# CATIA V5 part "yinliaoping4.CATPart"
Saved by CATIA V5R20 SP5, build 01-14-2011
Part number: 饮料瓶
Material "Multicoloured Flag"
Bounding box of the stored display mesh (mm): x -25 to 27, y -25 to 25, z 0 to 110
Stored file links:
  E:\0308\yinliaoping4.CATPart
  C:\Program Files\Dassault Systemes\B20\intel_a\startup\materials\Catalog.CATMaterial
  C:\Program Files\Dassault Systemes\B20\intel_a\startup\materials\chessboard.jpg
  C:\Program Files\Dassault Systemes\B20\intel_a\startup\materials\DS_star.jpg
  C:\Program Files\Dassault Systemes\B20\intel_a\startup\materials\solar_panel.jpg
  C:\Program Files\Dassault Systemes\B20\intel_a\startup\materials\sunset.jpg
  C:\Program Files\Dassault Systemes\B20\intel_a\startup\materials\summer_sky.jpg
  C:\Program Files\Dassault Systemes\B20\intel_a\startup\materials\raw_polystyren.jpg
  C:\Program Files\Dassault Systemes\B20\intel_a\startup\materials\strip_wall.jpg
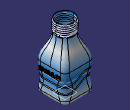
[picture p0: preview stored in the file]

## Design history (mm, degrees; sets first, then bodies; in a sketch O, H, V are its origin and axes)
Set1
  Sketch1 on xy-plane, origin (0, 0, 0), H (1, 0, 0), V (0, 1, 0)
    line L1 (25, 25) -> (25, -25)
    line L2 (25, -25) -> (-25, -25)
    line L3 (-25, -25) -> (-25, 25)
    line L4 (-25, 25) -> (25, 25)
    distance L2 L4 = 50
    distance L1 L3 = 50
    vertical: L1 V, L3 V
    horizontal: L2 H, L4 H
    equidistance: L1 L3 O, L2 L4 O
  Sketch2 on face of Pad1 from Sketch1.L2, origin (0, -25, 0), H (1, 0, 0), V (0, 0, 1)
    spline S1 through (-30, 20) (-10, 30) (10, 20) (30, 20)
  Extrude1: Element1 Sketch2, Lim1 20, Lim2 60
  Sketch3 on face of Pad1 from Sketch1.L2, origin (0, -25, 0), H (1, 0, 0), V (0, 0, 1)
    spline S1 through (-30, 30) (-10, 40) (10, 30) (30, 30)
  Extrude2: Element1 Sketch3, Lim1 56, Lim2 56
  MultiSel1: CommonCtxFeats ({extract ExtractElem face of Pad1 from Sketch1.L2}; {extract ExtractElem face of Fillet1}; {extract ExtractElem face of Pad1 from Sketch1.L1}; {extract ExtractElem face of Fillet1}; {extract ExtractElem face of Pad1 from Sketch1.L4}; {extract ExtractElem face of Fillet1}; {extract ExtractElem face of Pad1 from Sketch1.L3}; {extract ExtractElem face of Fillet1})
  MultiSel2: CommonCtxFeats ({extract ExtractElem face of Pad1 from Sketch1.L3}; {extract ExtractElem face of Fillet1}; {extract ExtractElem face of Pad1 from Sketch1.L2}; {extract ExtractElem face of Fillet1}; {extract ExtractElem face of Pad1 from Sketch1.L1}; {extract ExtractElem face of Fillet1}; {extract ExtractElem face of Pad1 from Sketch1.L4}; {extract ExtractElem face of Fillet1})
  Join1: Elements ({intersect ToIntersect1 {extract ExtractElem face of Pad1 from Sketch1.L3}, ToIntersect2 Extrude1}; {intersect ToIntersect1 {extract ExtractElem face of Fillet1}, ToIntersect2 Extrude1}; {intersect ToIntersect1 {extract ExtractElem face of Pad1 from Sketch1.L2}, ToIntersect2 Extrude1}; {intersect ToIntersect1 {extract ExtractElem face of Fillet1}, ToIntersect2 Extrude1}; {intersect ToIntersect1 {extract ExtractElem face of Pad1 from Sketch1.L1}, ToIntersect2 Extrude1}; {intersect ToIntersect1 {extract ExtractElem face of Fillet1}, ToIntersect2 Extrude1}; {intersect ToIntersect1 {extract ExtractElem face of Pad1 from Sketch1.L4}, ToIntersect2 Extrude1}; {intersect ToIntersect1 {extract ExtractElem face of Fillet1}, ToIntersect2 Extrude1})
  Join2: Elements ({intersect ToIntersect1 {extract ExtractElem face of Pad1 from Sketch1.L2}, ToIntersect2 Extrude2}; {intersect ToIntersect1 {extract ExtractElem face of Fillet1}, ToIntersect2 Extrude2}; {intersect ToIntersect1 {extract ExtractElem face of Pad1 from Sketch1.L1}, ToIntersect2 Extrude2}; {intersect ToIntersect1 {extract ExtractElem face of Fillet1}, ToIntersect2 Extrude2}; {intersect ToIntersect1 {extract ExtractElem face of Pad1 from Sketch1.L4}, ToIntersect2 Extrude2}; {intersect ToIntersect1 {extract ExtractElem face of Fillet1}, ToIntersect2 Extrude2}; {intersect ToIntersect1 {extract ExtractElem face of Pad1 from Sketch1.L3}, ToIntersect2 Extrude2}; {intersect ToIntersect1 {extract ExtractElem face of Fillet1}, ToIntersect2 Extrude2})
  Plane1: type Normal, Curve Join2, RefPoint vertex [face of MultiSel1 | face of MultiSel1]
  Circle1: type CtrRad, Start 0, End 180, Center vertex [face of MultiSel1 | face of MultiSel1], Support Plane1, Radius 1, FirstDirection (1, 0, 0)
Body1 (main body), material "Multicoloured Flag"
  Pad1: profile Sketch1, direction (0, 0, 1), length 50
  Fillet1: on edge [face of Pad1 from Sketch1.L1 | face of Pad1 from Sketch1.L2]; edge [face of Pad1 from Sketch1.L4 | face of Pad1 from Sketch1.L1]; edge [face of Pad1 from Sketch1.L3 | face of Pad1 from Sketch1.L4]; edge [face of Pad1 from Sketch1.L2 | face of Pad1 from Sketch1.L3]
  Plane2: type Offset, RefPlane end face of Pad1, Offset 40, reversed
  Sketch4 on Plane2, origin (0, 0, 90), H (1, 0, 0), V (0, -1, 0)
    circle A1 centre (0, 0) radius 15
    radius A1 = 15
  Pad2: profile Sketch4, direction (0, 0, 1), length 20
  Fillet2: on edge [start face of Pad1 | face of Pad1 from Sketch1.L3]
  Sketch5 on end face of Pad1, origin (0, 0, 50), H (1, 0, 0), V (0, 1, 0)
    point P1 (25, 0)
    distance V P1 = 25
    coincidence: P1 H
  Sketch6 on start face of Pad2, origin (0, 0, 90), H (1, 0, 0), V (0, -1, 0)
    point P1 (15, 0)
    distance V P1 = 15
    coincidence: P1 H
  Sketch7 on face of Pad1 from Sketch1.L2, origin (0, -25, 0), H (1, 0, 0), V (0, 0, 1)
  Loft1: solid, Sections ({boundary Boundary {extract ExtractElem end face of Pad1}}; {boundary Boundary {extract ExtractElem start face of Pad2}}), StartFace end face of Pad1, EndFace start face of Pad2
  Slot1: profile Circle1, centre curve Join2
  Plane3: type Normal, Curve Join1, RefPoint vertex [face of MultiSel2 | face of MultiSel2]
  Circle2: type CtrRad, Start 0, End 180, Center vertex [face of MultiSel2 | face of MultiSel2], Support Plane3, Radius 1, FirstDirection (1, 0, 0)
  Slot2: profile Circle2, centre curve Join1
  Shell1: ExtOffset 0, Face end face of Pad2, IntOffset 0.5
  Point1: type OnSurface, Support face of Pad2 from Sketch4.A1, RefPoint Sketch6, Length 2, Direction (0, 0, 1)
  Helix1: Direction Z axis, RefPoint Point1, Pitch 3, Height 16, TaperAngle 0
  Point2: type OnCurve, Support Helix1, RefPoint Point1, Length 5
  Point3: type OnCurve, Support Helix1, RefPoint vertex of Helix1, Length -5
  Line1: type PtDir, RefPoint Point1, Direction (1, 0, 0), Start 0, End 5
  Line2: type PtDir, RefPoint vertex of Helix1, Direction (0, 1, 0), Start 0, End 5
  Body2
    Sketch8 on Plane2, origin (0, 0, 90), H (1, 0, 0), V (0, -1, 0)
      circle A1 centre (0, 0) radius 14
      radius A1 = 14
    Pad3: profile Sketch8, direction (0, 0, -1), length 30, mirrored extent
  Remove1: tool Body2
  Sketch9 on Plane2, origin (0, 0, 90), H (1, 0, 0), V (0, -1, 0)
    circle A1 centre (0, 0) radius 14
  Pocket1: profile Sketch9, direction (0, 0, 1), length 30
  Pocket2: profile Sketch9, direction (0, 0, 1), length 30
  Pocket3: profile Sketch9, direction (0, 0, 1), length 23
  Pocket4: profile Sketch9, direction (0, 0, 1), length 23
  Sketch10 on Plane2, origin (0, 0, 90), H (1, 0, 0), V (0, -1, 0)
    circle A1 centre (0, 0) radius 14.5
Body3
  Sketch11 on face of Pad1 from Sketch1.L1, origin (25, 0, 0), H (0, 1, 0), V (0, 0, 1)
    polyline C1
    polyline C2
    polyline C3
    polyline C4
    polyline C5
    polyline C6
    polyline C7
    polyline C8
    polyline C9
    polyline C10
    polyline C11
  Pad4: profile Sketch11, direction (1, 0, 0), length 2
  Connect1: Curve1 Line1, Point1 vertex of Line1, Tension1 1, Curve2 Helix1, Point2 Point2, Tension2 1
  Connect2: Curve1 Line2, Point1 vertex of Line2, Tension1 1, Curve2 Connect1, Point2 Point3, Tension2 1
  Plane4: type Normal, Curve Connect2, RefPoint vertex of Connect2
  Plane5: type Normal, Curve Connect2, RefPoint vertex of Connect1
  Circle3: type CtrRad, Start 0, End 180, Radius 1, Center vertex of Connect2, Support Plane4, FirstDirection (-1, 0, 0)
  Circle4: type CtrRad, Start 0, End 180, Radius 1, Center vertex of Connect1, Support Plane5, FirstDirection (0, -1, 0)
  Rib1: profile Circle3, centre curve Connect2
